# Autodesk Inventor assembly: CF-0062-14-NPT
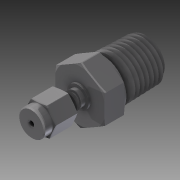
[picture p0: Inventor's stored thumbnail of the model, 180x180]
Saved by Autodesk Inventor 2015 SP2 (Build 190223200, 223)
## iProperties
Created: 2017-11
Part Number: CF-0062-14-NPT
Document SubType Name: Assembly
Designer: JN
Author: JN
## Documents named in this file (4)
- C:\Users\JN\Documents\CAD Drawings\The Sensor Connection\3D\CF\CF-0062-NPT\CF-0062-14-NPT.iam
- C:\Users\JN\Documents\CAD Drawings\The Sensor Connection\3D\CF\CF-0062-NPT\Imported Components\CF-0062-NPT Bottom Ferrule\CF-0062-NPT Bottom Ferrule.ipt
- C:\Users\JN\Documents\CAD Drawings\The Sensor Connection\3D\CF\CF-0062-NPT\Imported Components\CF-0062-NPT Cap\CF-0062-NPT Cap.ipt
- C:\Users\JN\Documents\CAD Drawings\The Sensor Connection\3D\CF\CF-0062-NPT\Imported Components\CF-0062-14-NPT Threaded Body\CF-0062-14-NPT Threaded Body.ipt
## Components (3 placed, 3 different names)
1. CF-0062-NPT Bottom Ferrule:1 — Mate:7, Mate:8, Mate:10
2. CF-0062-NPT Cap:1 — Mate:7, Mate:8, Mate:9, Rotation:1
3. CF-0062-14-NPT Threaded Body:1 — Mate:9, Mate:10, Rotation:1
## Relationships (5: Mate 4, RelateRotation 1)
- Mate:7: CF-0062-NPT Bottom Ferrule:1 ↔ CF-0062-NPT Cap:1
- Mate:8: CF-0062-NPT Bottom Ferrule:1 ↔ CF-0062-NPT Cap:1
- Mate:9: CF-0062-NPT Cap:1 ↔ CF-0062-14-NPT Threaded Body:1
- Mate:10: CF-0062-NPT Bottom Ferrule:1 ↔ CF-0062-14-NPT Threaded Body:1
- Rotation:1 [RelateRotation]: CF-0062-NPT Cap:1 ↔ CF-0062-14-NPT Threaded Body:1
